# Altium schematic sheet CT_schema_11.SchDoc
size 741 x 377 mm
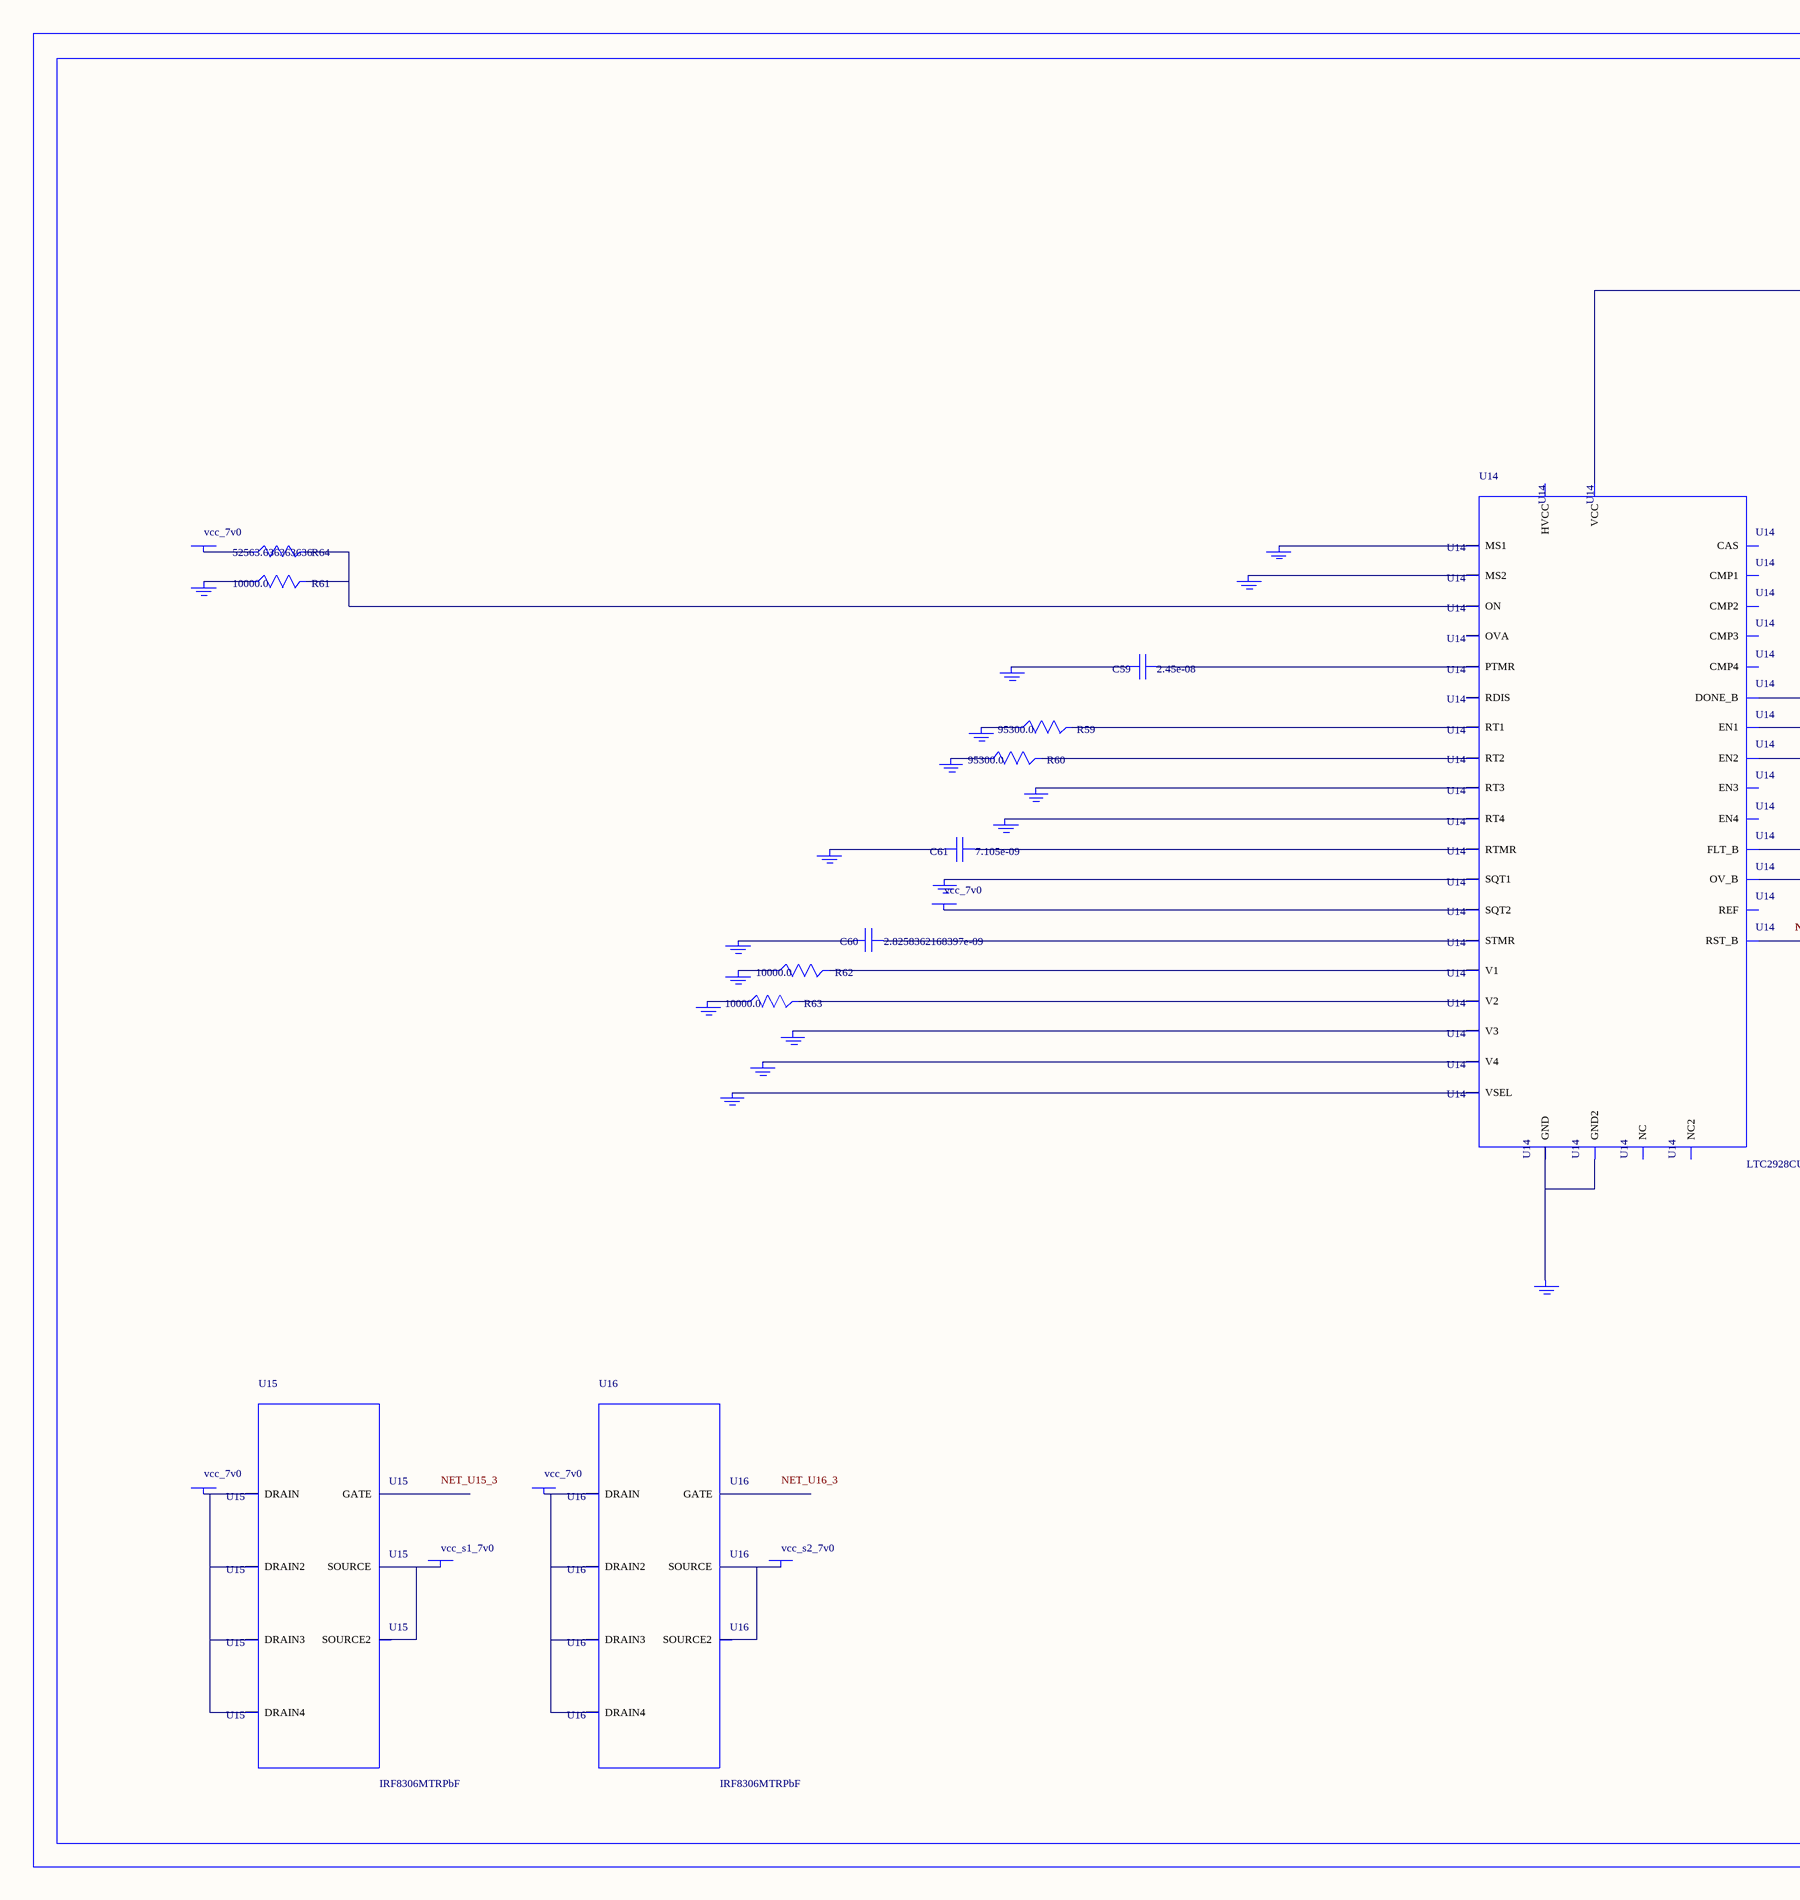
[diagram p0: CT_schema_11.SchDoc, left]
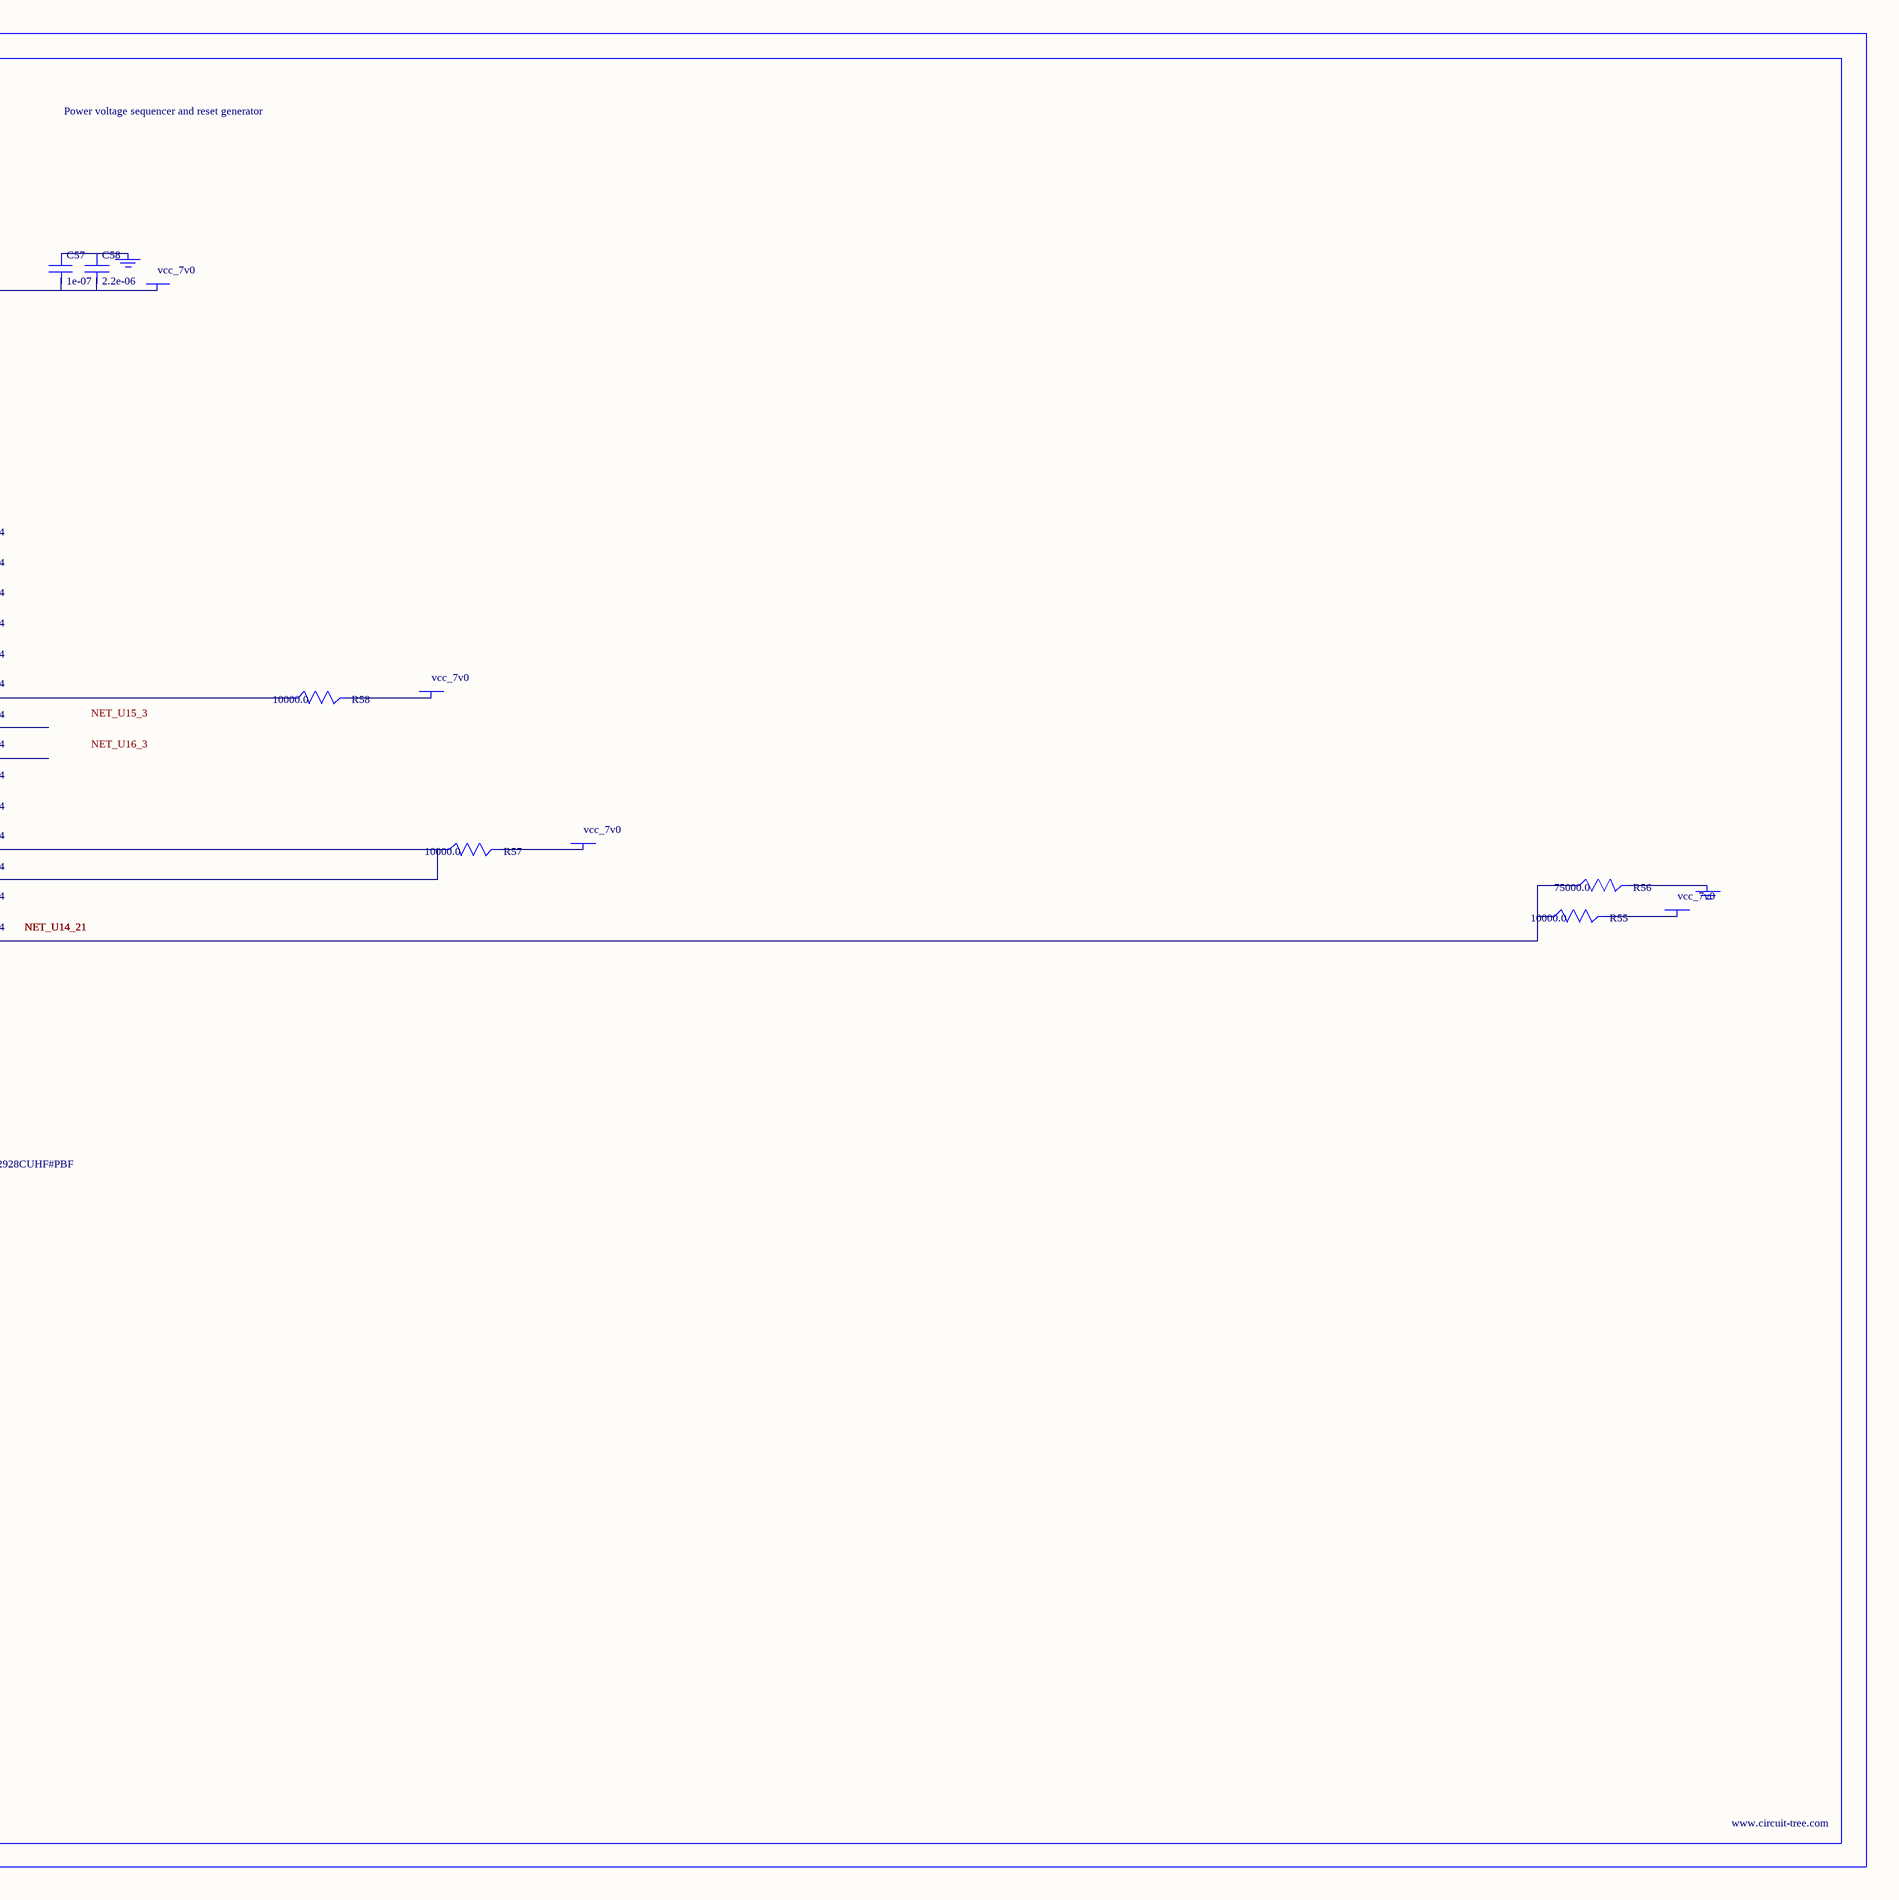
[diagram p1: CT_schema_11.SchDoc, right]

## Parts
BORDER10  (no value)
C57  1e-07  [C0402]
C58  2.2e-06  [C0603]
C59  2.45e-08  [R0603]
C60  2.8258362168397e-09  [R0603]
C61  7.105e-09  [R0603]
GND_INSTANCE_10_0  (no value)
GND_INSTANCE_10_1  (no value)
GND_INSTANCE_10_2  (no value)
GND_INSTANCE_10_3  (no value)
GND_INSTANCE_10_4  (no value)
GND_INSTANCE_10_5  (no value)
GND_INSTANCE_10_6  (no value)
GND_INSTANCE_10_7  (no value)
GND_INSTANCE_10_8  (no value)
GND_INSTANCE_10_9  (no value)
GND_INSTANCE_10_10  (no value)
GND_INSTANCE_10_11  (no value)
GND_INSTANCE_10_12  (no value)
GND_INSTANCE_10_13  (no value)
GND_INSTANCE_10_14  (no value)
GND_INSTANCE_10_15  (no value)
GND_INSTANCE_10_16  (no value)
GND_INSTANCE_10_17  (no value)
GND_INSTANCE_10_18  (no value)
POWER_INSTANCE_10_0  vcc_7v0
POWER_INSTANCE_10_1  vcc_7v0
POWER_INSTANCE_10_2  vcc_7v0
POWER_INSTANCE_10_3  vcc_7v0
POWER_INSTANCE_10_4  vcc_7v0
POWER_INSTANCE_10_5  vcc_7v0
POWER_INSTANCE_10_6  vcc_7v0
POWER_INSTANCE_10_7  vcc_s1_7v0
POWER_INSTANCE_10_8  vcc_7v0
POWER_INSTANCE_10_9  vcc_s2_7v0
R55  10000.0  [R0603]
R56  75000.0  [R0603]
R57  10000.0  [R0603]
R58  10000.0  [R0603]
R59  95300.0  [R0603]
R60  95300.0  [R0603]
R61  10000.0  [R0603]
R62  10000.0  [R0603]
R63  10000.0  [R0603]
R64  52563.636363636  [R0603]
U14  LTC2928CUHF#PBF  [QFN-38_UHF]
U15  IRF8306MTRPbF  [IRF8306MTRPBF]
U16  IRF8306MTRPbF  [IRF8306MTRPBF]

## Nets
NetC57_1: C57.1 C58.1 GND_INSTANCE_10_10.0(GND)
NetC57_2: C57.2 C58.2 POWER_INSTANCE_10_5.0(PWR) U14.22(VCC)
NetC59_1: C59.1 U14.27(PTMR)
NetC59_2: C59.2 GND_INSTANCE_10_13.0(GND)
NetC60_1: C60.1 U14.26(STMR)
NetC60_2: C60.2 GND_INSTANCE_10_12.0(GND)
NetC61_1: C61.1 U14.28(RTMR)
NetC61_2: C61.2 GND_INSTANCE_10_14.0(GND)
NetGND_INSTANCE_10_0_0: GND_INSTANCE_10_0.0(GND) R62.1
NetGND_INSTANCE_10_1_0: GND_INSTANCE_10_1.0(GND) R59.1
NetGND_INSTANCE_10_2_0: GND_INSTANCE_10_2.0(GND) R60.1
NetGND_INSTANCE_10_3_0: GND_INSTANCE_10_3.0(GND) U14.8(RT3)
NetGND_INSTANCE_10_4_0: GND_INSTANCE_10_4.0(GND) U14.9(RT4)
NetGND_INSTANCE_10_5_0: GND_INSTANCE_10_5.0(GND) U14.10(SQT1)
NetGND_INSTANCE_10_6_0: GND_INSTANCE_10_6.0(GND) U14.12(MS1)
NetGND_INSTANCE_10_7_0: GND_INSTANCE_10_7.0(GND) U14.13(MS2)
NetGND_INSTANCE_10_8_0: GND_INSTANCE_10_8.0(GND) R61.1
NetGND_INSTANCE_10_9_0: GND_INSTANCE_10_9.0(GND) R56.2
NetGND_INSTANCE_10_11_0: GND_INSTANCE_10_11.0(GND) U14.25(VSEL)
NetGND_INSTANCE_10_15_0: GND_INSTANCE_10_15.0(GND) U14.30(V4)
NetGND_INSTANCE_10_16_0: GND_INSTANCE_10_16.0(GND) U14.32(V3)
NetGND_INSTANCE_10_17_0: GND_INSTANCE_10_17.0(GND) R63.1
NetGND_INSTANCE_10_18_0: GND_INSTANCE_10_18.0(GND) U14.24(GND) U14.39(GND2)
NetPOWER_INSTANCE_10_0_0: POWER_INSTANCE_10_0.0(PWR) U14.11(SQT2)
NetPOWER_INSTANCE_10_1_0: POWER_INSTANCE_10_1.0(PWR) R64.1
NetPOWER_INSTANCE_10_2_0: POWER_INSTANCE_10_2.0(PWR) R58.2
NetPOWER_INSTANCE_10_3_0: POWER_INSTANCE_10_3.0(PWR) R57.2
NetPOWER_INSTANCE_10_4_0: POWER_INSTANCE_10_4.0(PWR) R55.2
NetPOWER_INSTANCE_10_6_0: POWER_INSTANCE_10_6.0(PWR) U15.1(DRAIN) U15.2(DRAIN2) U15.6(DRAIN3) U15.7(DRAIN4)
NetPOWER_INSTANCE_10_7_0: POWER_INSTANCE_10_7.0(PWR) U15.4(SOURCE) U15.5(SOURCE2)
NetPOWER_INSTANCE_10_8_0: POWER_INSTANCE_10_8.0(PWR) U16.1(DRAIN) U16.2(DRAIN2) U16.6(DRAIN3) U16.7(DRAIN4)
NetPOWER_INSTANCE_10_9_0: POWER_INSTANCE_10_9.0(PWR) U16.4(SOURCE) U16.5(SOURCE2)
NetR55_1: R55.1 R56.1 U14.21(RST_B)
NetR57_1: R57.1 U14.19(FLT_B) U14.20(OV_B)
NetR58_1: R58.1 U14.18(DONE_B)
NetR59_2: R59.2 U14.6(RT1)
NetR60_2: R60.2 U14.7(RT2)
NetR61_2: R61.2 R64.2 U14.16(ON)
NetR62_2: R62.2 U14.3(V1)
NetR63_2: R63.2 U14.38(V2)

Not connected (* = marked no-connect by the designer): U14 1(OVA) 2(EN1) 4(NC) 5(REF) 14(RDIS) 15(CAS) 17(NC2) 23(HVCC) 29(EN4) 31(EN3) 33(CMP3) 34(CMP4) 35(CMP1) 36(CMP2) 37(EN2); U15 3(GATE); U16 3(GATE)

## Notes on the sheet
- Labels drawn without touching a wire or pin: NET_U15_3, NET_U16_3

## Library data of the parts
BORDER10 = BORDER_PAGE10
C57 = C0402C104K3RACTU
C58 = GRM188R61H225KE1115D
C59 = C59
C60 = C60
C61 = C61
GND_INSTANCE_10_0-GND_INSTANCE_10_18 = GND
POWER_INSTANCE_10_0-POWER_INSTANCE_10_9 = PWR
R55 R57 R58 R61-R63 = RC0603JR-0710KL
R56 = RC0603JR-0775KL
R59 R60 = RC0603FR-0795K3L
R64 = R64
